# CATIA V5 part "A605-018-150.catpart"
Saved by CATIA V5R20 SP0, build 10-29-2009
Part number: A605-018-150
Source: Unknown
Property "A": "0.000"
Property "ARTICLENO": "A605-018-150"
Property "BOMINFO": "A605-018-150"
Property "CODE": "A605-018-150"
Property "D": "6.500"
Property "FORM": "B"
Property "L": "150.000"
Property "L1": "60.000"
Property "LINA": "A605-018-150"
Property "NB": "A605-018-150"
Property "NBSYN": "$CODE."
Property "NN": "A605"
Property "NT": "Wear Plates, self-lubricating"
Property "SCREW": "3*M6X10"
Property "SUPPLIER": "CF"
Property "W": "18.000"
Bounding box of the stored display mesh (mm): x -18 to 0, y 0 to 5, z -150 to 0
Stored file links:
  C:\Users\Utente\Desktop\3D files A605\A605-018-150.catpart
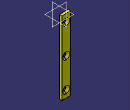
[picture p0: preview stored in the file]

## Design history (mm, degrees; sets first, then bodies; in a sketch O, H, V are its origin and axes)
Body1 "Geometry.1" (main body)
  Solid1 "A605-018-150.catpart": solid without history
